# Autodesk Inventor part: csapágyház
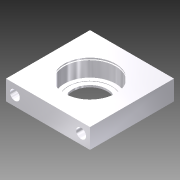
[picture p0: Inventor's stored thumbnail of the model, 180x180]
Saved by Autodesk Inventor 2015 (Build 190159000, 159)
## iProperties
Created: 2012-12
Part Number: csapágyház
Material: Generic
Document SubType Name: Modeling
Designer: Dani
Density: 1 g/cm^3
Appearance: Aluminum - Polished
Author: Dani
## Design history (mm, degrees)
sketch "Sketch1"
  geometry: L1 (-42.5, 42.5)-(42.5, 42.5); L2 (42.5, 42.5)-(42.5, -42.5); L3 (42.5, -42.5)-(-42.5, -42.5); L4 (-42.5, -42.5)-(-42.5, 42.5); L5 (0, 59.5)-(0, -59.5) reference; L6 (-59.5, 0)-(59.5, 0) reference; 1 further point
  constraints: 8 end point, 2 parallel, 1 horizontal, 1 perpendicular, 2 other
  dimensions: "d0" = 85 distance of L1.start L1.end; "d1" = 85 distance of L3.end L1.start
extrude "Extrusion1" new body sketch "Sketch1" distance "d2" = 20; taper "d3" = 0 deg
sketch "Sketch2"
  geometry: C1 r 26 at (0, 0); 1 further point
  constraints: 1 centre point, 1 coincident
  dimensions: "d4" = 52 diameter of C1
extrude "Extrusion2" cut sketch "Sketch2" distance "d5" = 18; taper "d6" = 0 deg
sketch "Sketch3"
  geometry: C1 r 26 at (0, 0) reference; C2 r 17.5 at (0, 0)
  constraints: 1 centre point, 1 coincident
  dimensions: "d7" = 35 diameter of C2
extrude "Extrusion3" cut sketch "Sketch3" stored distance "d8" = 16; taper "d9" = 0 deg
sketch "Sketch4"
  geometry: L1 (26, 2)-(-26, 2) reference; L2 (-26, 20)-(-26, 2) reference; L3 (-26, 2)-(-22, 2); L4 (-22, 2)-(-22, 2.5); L5 (-22, 2.5)-(-26, 2.5); L6 (-26, 2)-(-26, 2.5); L7 (0, -4)-(0, 24) reference; 1 further point
  constraints: 8 end point, 3 perpendicular, 2 point on line
  dimensions: "d10" = 4 distance of L2.end L3.end; "d11" = 0.5 distance of L3.end L4.end
revolve "Revolution1" sketch "Sketch4" stored, may be unused: angle "d12" = 90 deg
sketch "Sketch5"
  geometry: L1 (42.5, 20)-(-42.5, 20) reference; L2 (-42.5, 0)-(-42.5, 20) reference; L3 (42.5, 0)-(-42.5, 0) reference; L4 (42.5, 0)-(42.5, 20) reference; L5 (-26, 20)-(-26, 2.5) reference; L6 (-26, 19.1)-(-26, 17.8); L7 (-26, 17.8)-(-27.2, 17.8); L8 (-27.2, 17.8)-(-27.2, 19.1); L9 (-27.2, 19.1)-(-26, 19.1); L10 (0, -4)-(0, 24) reference; 1 further point
  constraints: 8 end point, 2 perpendicular, 1 parallel, 1 point on line
  dimensions: "d14" = 2.2 distance of L5.start L6.end; "d15" = 1.2 distance of L6.end L7.end; "d16" = 1.3 distance of L7.end L8.end
revolve "Revolution2" sketch "Sketch5" stored, may be unused: angle "d17" = 90 deg
sketch "Sketch6"
  geometry: L1 (0, 0)-(0, -20) reference; C1 r 5 at (9, -10); 1 further point
  constraints: 1 centre point
  dimensions: "d18" = 10 diameter of C1; "d19" = 9 distance from line of C1.centre L1
extrude "Extrusion4" cut sketch "Sketch6" stored distance "d20" = 16; taper "d21" = 0 deg
workplane "Work Plane2"
sketch "Sketch7"
  geometry: C1 r 5 at (9, -10) reference; C2 r 8 at (9, -10); 1 further point
  constraints: 1 centre point, 1 coincident
  dimensions: "d23" = 16 diameter of C2
extrude "Extrusion5" cut sketch "Sketch7" distance "d24" = 9; taper "d25" = 0 deg
mirror "Mirror1"
body "Solid1"
node "Projected Loop1"
